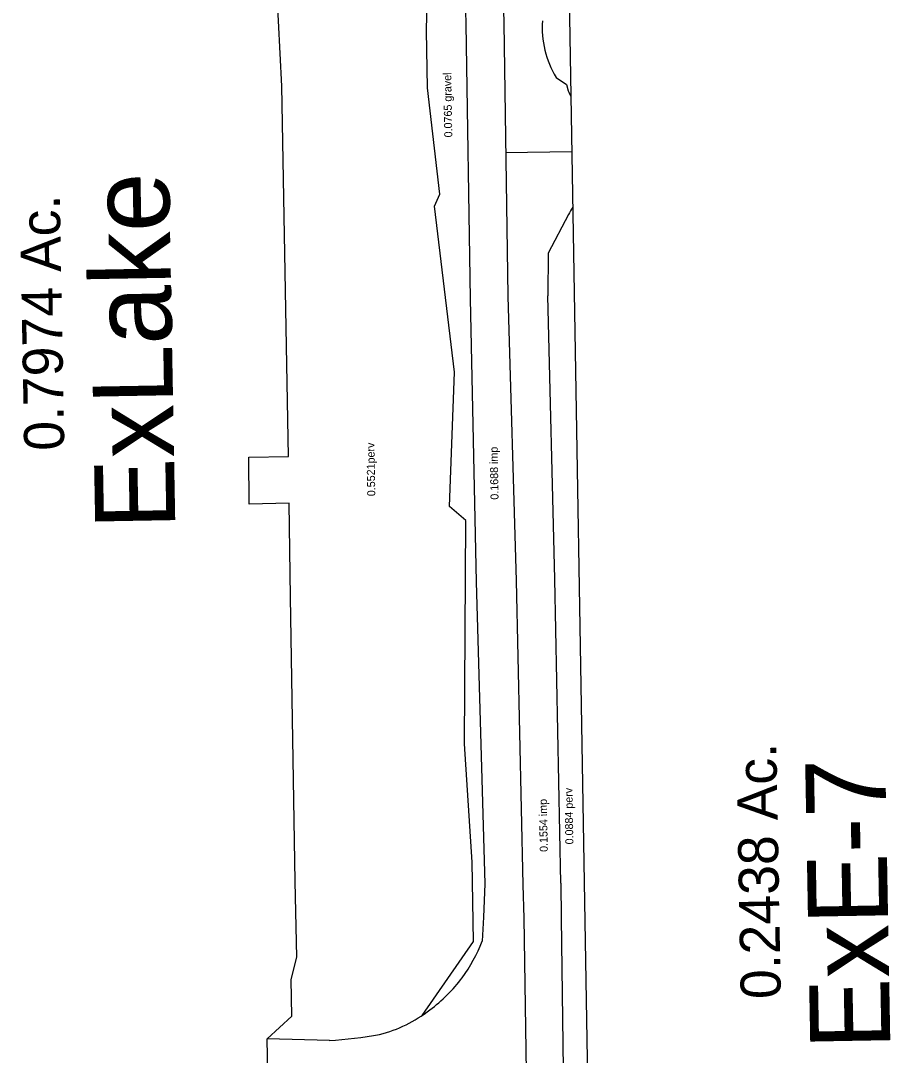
# Model space of a CAD drawing. Extents: x 925564 to 926134, y 853260 to 858402.
# Drawn here: x 925630.4 to 925934.3, y 855605.9 to 855967.9 of the extents above; entities that cross this region are included whole.
import ezdxf

# ---------------------------------------------------------------- set-up
doc = ezdxf.new("R2010")
doc.units = 0
for name, color, linetype in [('DrainDivides01', 7, 'Continuous'), ('PavtMisc_ep', 7, 'Continuous'), ('TextLabel', 7, 'Continuous')]:
    doc.layers.add(name, color=color, linetype=linetype)

msp = doc.modelspace()

# ---------------------------------------------------------------- linework, layer by layer
at = {"layer": 'DrainDivides01'}
for p, q in [((925796.98, 856064.9), (925799.24, 855966.98)), ((925821.38, 856018.6), (925832.59, 855359.55)), ((925799.24, 855966.98), (925800.61, 855871.45)), ((925723.08, 855866.9), (925721.66, 855945.02)), ((925823.03, 855921.94), (925799.89, 855921.61)), ((925800.61, 855871.45), (925803.62, 855771.95)), ((925723.98, 855815.45), (925723.08, 855866.9)), ((925710.06, 855815.13), (925723.98, 855815.45)), ((925710.27, 855798.75), (925710.06, 855815.13)), ((925724.24, 855799.09), (925710.27, 855798.75)), ((925724.73, 855766.2), (925724.24, 855799.09)), ((925803.62, 855771.95), (925805.84, 855665.58)), ((925726.31, 855666.72), (925724.73, 855766.2)), ((925726.84, 855640.31), (925726.31, 855666.72)), ((925805.84, 855665.58), (925806.2, 855653.89)), ((925806.2, 855653.89), (925807.06, 855600.15))]:
    msp.add_line(p, q, dxfattribs=at)
for points in [[(925721.66, 855945.02), (925719.94, 855979.33), (925732.98, 856040.62), (925720.92, 856112.52), (925719.77, 856168.28), (925723.01, 856207.1)], [(925734.79, 855578.34), (925716.98, 855586.89), (925716.56, 855611.72), (925725.15, 855619.58), (925724.94, 855632.41), (925726.84, 855640.31)]]:
    msp.add_lwpolyline(points, dxfattribs=at)
at = {"layer": 'PavtMisc_ep'}
for p, q in [((925783.38, 856064.34), (925786, 855966.7)), ((925786, 855966.7), (925787.5, 855870.57)), ((925817.5, 855947.98), (925821.12, 855945.57)), ((925821.12, 855945.57), (925821.75, 855943.37)), ((925821.83, 855900.02), (925814.73, 855886.49)), ((925814.73, 855886.49), (925814.67, 855871.62)), ((925787.5, 855870.57), (925789.62, 855771.54)), ((925817.03, 855772.49), (925814.67, 855871.62)), ((925789.62, 855771.54), (925792.57, 855665.87)), ((925819.13, 855666.1), (925817.03, 855772.49)), ((925792.57, 855665.87), (925792.11, 855654.24)), ((925819.13, 855666.1), (925819.33, 855653.94)), ((925792.11, 855654.24), (925791.71, 855645.82)), ((925819.33, 855653.94), (925820.02, 855601.13)), ((925738.26, 855611.12), (925716.56, 855611.67))]:
    msp.add_line(p, q, dxfattribs=at)
msp.add_lwpolyline([(925770.66, 855619.85), (925788.69, 855645.75), (925788.22, 855673.53), (925785.48, 855714.94), (925786.03, 855792.98), (925780.29, 855797.91), (925782.01, 855844.89), (925775.05, 855903.02), (925776.87, 855907.13), (925772.62, 855944.43), (925772.28, 855964.37), (925773.67, 856030.34), (925773.28, 856053.41), (925772.71, 856087.16), (925762.83, 856104.58), (925756.76, 856109.48)], dxfattribs=at)
for centre, major_axis, ratio, start_param, end_param in [((925847.43, 855965.66), (3.87, -34.55), 0.999962, 4.537152, 5.134306), ((925839.29, 855950.16), (11.21, 15.09), 0.999801, 2.579197, 2.699899), ((925841.18, 855890.17), (-13.94, 16.66), 0.999814, 0.265919, 0.40322), ((925736.57, 855667.81), (43.37, 40.57), 0.999311, 4.905773, 5.151307), ((925741.81, 855664.95), (-8.05, -52.85), 0.999473, 0.783802, 1.083086), ((925744.39, 855658.9), (33.59, 33.12), 0.997565, 4.180595, 4.59841), ((925728.84, 855763.87), (-130.35, 80.25), 0.999648, 2.184051, 2.299768)]:
    msp.add_ellipse(centre, major_axis=major_axis, ratio=ratio, start_param=start_param, end_param=end_param, dxfattribs=at)

# ---------------------------------------------------------------- texts
at = {"layer": 'TextLabel'}
for s, height, p in [('0.0765 gravel', 2.8, (925781.25, 855927.08)), ('ExLake', 28, (925684.44, 855790.1)), ('0.7974 Ac.', 14, (925645.62, 855817.56)), ('0.5521perv', 2.8, (925754.33, 855801.55)), ('0.1688 imp', 2.8, (925797.42, 855800.33)), ('0.2438 Ac.', 14, (925896.1, 855625.74)), ('ExE-7', 28, (925934.4, 855608.16)), ('0.0884 perv', 2.8, (925823.58, 855679.75)), ('0.1554 imp', 2.8, (925814.63, 855677.11))]:
    msp.add_text(s, height=height, rotation=91.0261, dxfattribs=at).set_placement(p)

doc.saveas('drawing.dxf')
